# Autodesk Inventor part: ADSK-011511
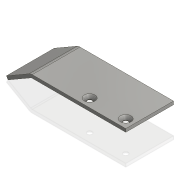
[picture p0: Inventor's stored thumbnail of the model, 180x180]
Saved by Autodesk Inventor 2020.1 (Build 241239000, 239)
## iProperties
Created: 2000-02
Part Number: ADSK-011511
Material: 1.0312 DC05
Description: FSHTPH,SS,CP,01,044,006,030,PLATE,GUIDE
Document SubType Name: Tôlerie
Designer: sspink
Density: 1 g/cm^3
Sheet Metal Rule: Stahlblech 1.0312 - DC05 -   3.0 mm
Appearance: Stahl
Mass: 15.2857 g
Surface Area: 113.1 cm^2
Volume: 15.2857 cm^3
Flat Pattern Width: 9.64483 cm
Flat Pattern Length: 12.2053 cm
Flat Pattern Area: 117.718 cm^2
Sheet Metal Width: 96,448 mm
Sheet Metal Length: 122,053 mm
Sheet Metal Area: 11771,830 mm^2
Control State: 0
Checked Out: False
Master: False
Shininess: 57.0
Length Units: 11269
Angle Units: 11279
Time Units: 11290
Mass Units: 11283
Length Display Precision: 3
Angle Display Precision: 2
Compacted: True
CUTLENGTH: 1.75 X 4.53 (8 SI)
MATERIAL DESC: SHEET,S/S, 11 GA
MATERIAL_NUMBER: A084638
G_L: 122,1x96,4 mm
Thickness: 3,000 mm
Dimensions: 112,4x15,7x45 mm
Mass: 0,015 kg
Semi finished: Stahlblech 1.0312 - DC05 -   3.0 mm
Density: 0.0
Volumn: 0.0
Area: 0.0
PropertySet Name: Model Information
Author: sspink
Revision Number: -
Title: FSHTPH,SS,CP,01,044,006,030,PLATE,GUIDE
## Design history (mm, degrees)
node "Solide1"
  node "Extrusion1" dims "d2" = 45, "d3" = 0
  node "Hole1" dims "d11" = 4.5, "d12" = 10, "d13" = 6.35, "d14" = 90 deg, "d15" = 19.05, "d16" = 118 deg, "d23" = 6
  node "Bend1" dims "d17" = 3 (= BendRadius), "d18" = 3 (= BendReliefWidth), "d19" = 1.5 (= BendReliefDepth), "d20" = 6 (= MinimumRemnant), "d21" = 3 (= Thickness), "SeamGap" = 0.00508, "MinimumRemnant" = 6 (= 2 x Thickness), "BendReliefWidth" = 3 (= Thickness)
sketch "Sketch1"
  geometry: L1 (0, 0)-(88.9, 0); L2 (88.9, 0)-(88.9, 3); L3 (88.9, 3)-(0, 3); L4 (0, 3)-(0, 0); L5 (0, 0)-(-21.997, -12.7); L6 (-21.997, -12.7)-(-23.497, -10.102); L7 (-23.497, -10.102)-(-0.804, 3); L8 (0, 3)-(-0.804, 3)
  constraints: 16 end point, 3 parallel, 3 perpendicular, 1 horizontal
  dimensions: "d0" = 3 distance between parallel lines of L1 L3 (= Thickness); "d1" = 88.9 distance of L2.end L3.end; "d4" = 25.4 distance of L1.start L5.end; "d5" = 3 distance between parallel lines of L5 L7 (= Thickness); "d6" = 150 deg angle of L1 L5
sketch "Sketch2"
  geometry: L1 (0, -45)-(89.704, -45) reference; L2 (89.704, 0)-(89.704, -45) reference; 2 further points
  constraints: 1 horizontal alignment
  dimensions: "d7" = 8 distance from line of point (81.704, -37) L2; "d10" = 8 distance from line of L1 point (81.704, -37); "d22" = 34 distance of point (81.704, -37) point (47.704, -37)
node "FlatPattern"
node "Corps solides"
node "Corps surfaciques"
feature "Extrusion_mise_à_plat2" dims "d0" = 3 (derived)
other parameters: "thickness" = 3.175 [user parameter], "Thickness" = 3 (derived), "BendRadius" = 3 (= Thickness), "BendReliefDepth" = 1.5 (= 0.5 x Thickness), "CornerReliefSize" = 12 (= 4 x Thickness), "TransitionRadius" = 3 (= BendRadius), "TailleRayonJacobi" = 3 (= BendRadius), "TailleJeu" = 3 (= Thickness)
